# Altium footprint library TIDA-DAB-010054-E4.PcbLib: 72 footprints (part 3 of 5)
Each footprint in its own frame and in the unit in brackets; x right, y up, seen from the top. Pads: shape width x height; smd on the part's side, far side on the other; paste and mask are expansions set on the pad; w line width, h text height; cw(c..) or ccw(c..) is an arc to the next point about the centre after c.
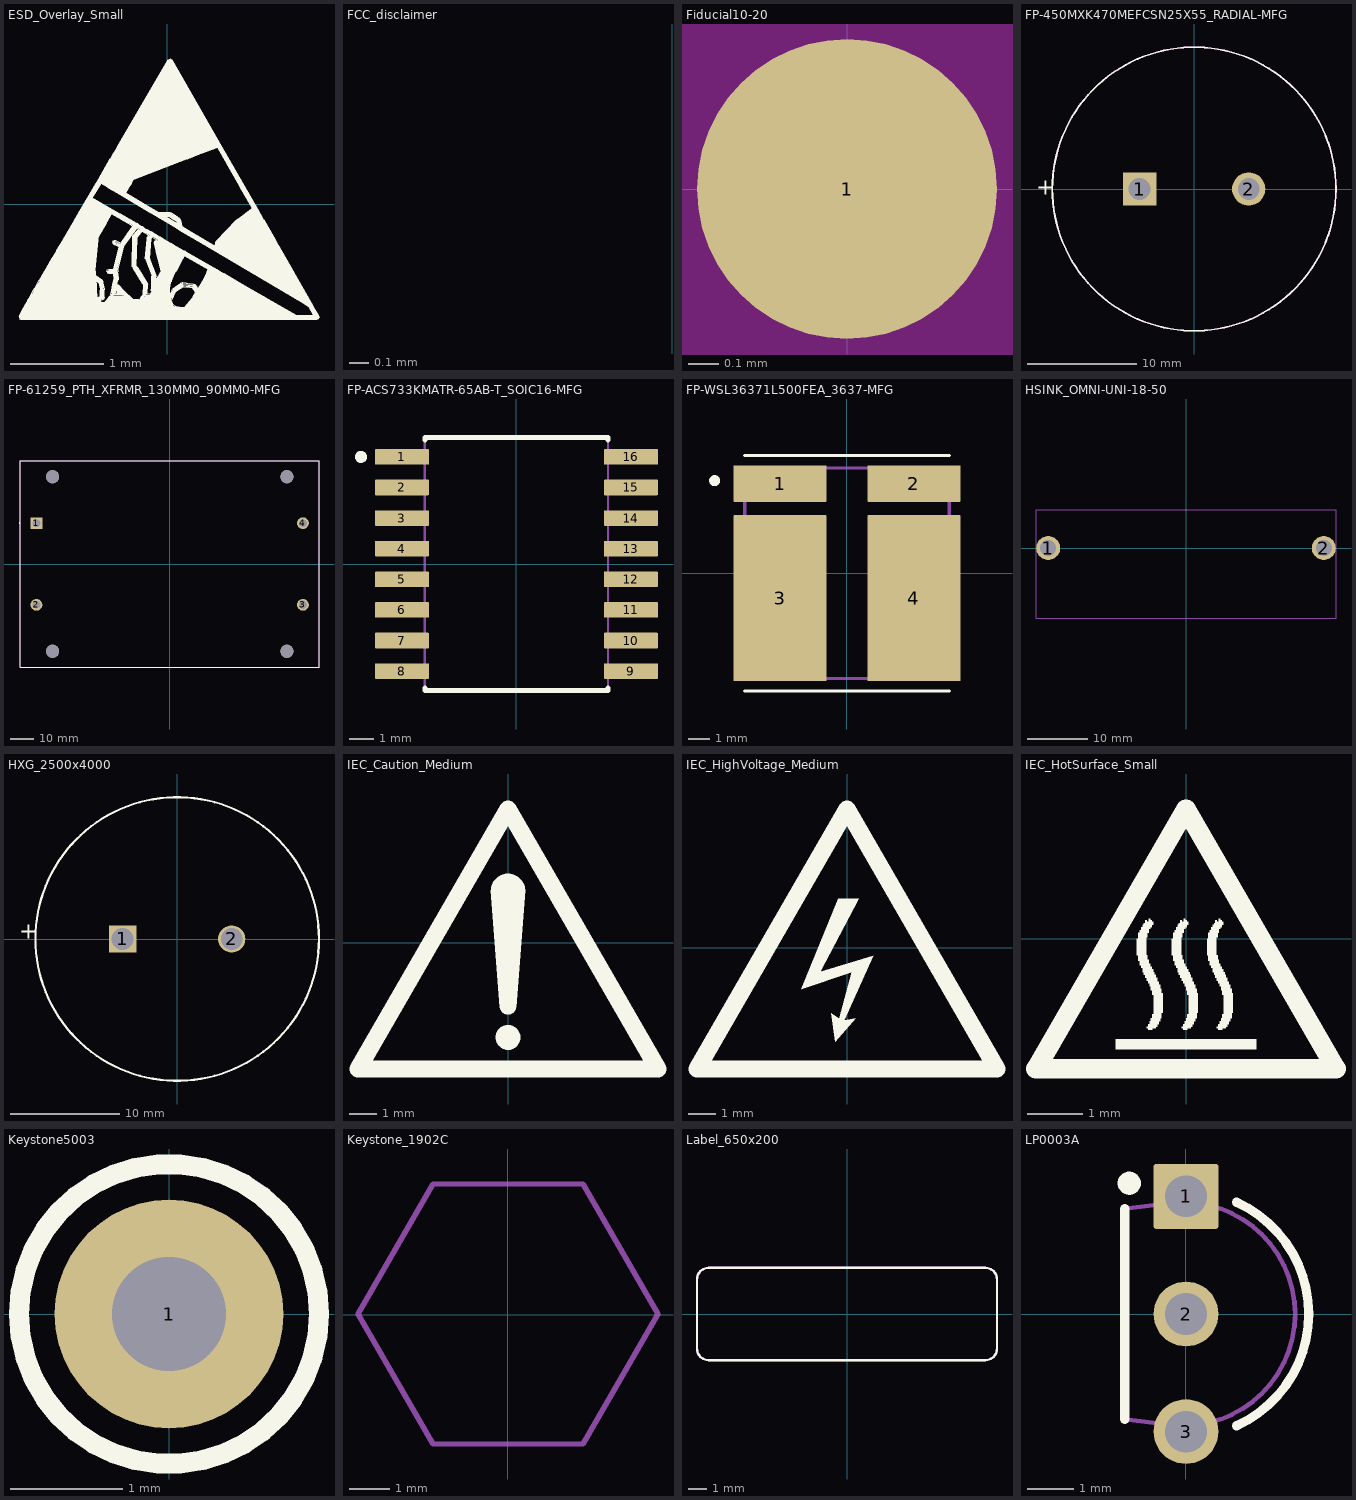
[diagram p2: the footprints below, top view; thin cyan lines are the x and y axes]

## ESD_Overlay_Small [mm]
height 9.2
Top Overlay:
  drawing of 901 lines, arcs and shapes, not listed

## FCC_disclaimer [mm]
height 9.2
Top Overlay:
  text "For evaluation only; not FCC approved for resale." at -1.598,12.423 h1.52

## Fiducial10-20 [mm]
height 9.2
pads (1):
  round 1 smd mask+0.5: 1(0,0)
Top Layer keep-out:
  circle w1.178: c0,0 r0.5

## FP-450MXK470MEFCSN25X55_RADIAL-MFG [mm]
pads (2):
  rrect3% 3.05x3.05 hole 2 paste-1000 mask+0: 1(-5,0)
  round 3.05 hole 2 paste-1000 mask+0: 2(5,0)
Top Overlay:
  circle w0.15: c0,0 r13
  text "+" at -14.5,-0.508 h1.5
Mechanical 5:
  circle w0.15: c0,0 r13
  text ".Designator" at -0.229,0.676 h0.51
  text "+" at -13.64,-0.492 h0.51
3D body "Cap_450MXK470MEFCSN25X55_RADIAL.STEP": height 0.25, standoff 0, extent -13.1,-13.1 13.1,13.1

## FP-61259_PTH_XFRMR_130MM0_90MM0-MFG [mm]
height 9.2
pads (8):
  rrect2% 5.15x5.15 hole 3.4 paste-1000 mask+0: 1(-58.02,17.78)
  round 5.15 hole 3.4 paste-1000 mask+0: 2(-58.02,-17.78) 4(58.02,17.78)
  round 5.15 hole 3.6 paste-1000 mask+0: 3(58.02,-17.78)
  round 5.7 hole 5.7 unplated paste-1000 mask+0: ""(-51,-38) ""(-51,38) ""(51,-38) ""(51,38)
Top Overlay:
  circle w0.25: c-65.5,17.78 r0.125
  lines w0.15: -65,-45 -65,45 65,45 65,-45 -65,-45
Mechanical 5:
  lines w0.15: -65,-45 -65,45 65,45 65,-45 -65,-45
  text ".Designator" at -58.167,24.194 h0.51
3D body "Payton Planar 61259 rev3.step": height 52, standoff 0, extent -65,-45 65,45

## FP-ACS733KMATR-65AB-T_SOIC16-MFG [mm]
height 9.2
pads (16):
  rrect15% 2.25x0.65 smd paste+0 mask+0: 1(-4.75,4.445) 2(-4.75,3.175) 3(-4.75,1.905) 4(-4.75,0.635) 5(-4.75,-0.635) 6(-4.75,-1.905) 7(-4.75,-3.175) 8(-4.75,-4.445) 9(4.75,-4.445) 10(4.75,-3.175) 11(4.75,-1.905) 12(4.75,-0.635) 13(4.75,0.635) 14(4.75,1.905) 15(4.75,3.175) 16(4.75,4.445)
Top Overlay:
  circle w0.25: c-6.45,4.445 r0.125
  lines w0.2: -3.8,-5.145 -3.8,-5.25 3.8,-5.25 3.8,-5.145 ; -3.8,5.145 -3.8,5.25 3.8,5.25 3.8,5.145
Mechanical 5:
  lines w0.1: -3.8,-5.25 -3.8,5.25 3.8,5.25 3.8,-5.25 -3.8,-5.25
  text ".Designator" at 0.134,-0.209 h0.51
3D body "IC_ACS733KMATR-65AB-T_SOIC16.STEP": height 0.25, standoff 0, extent -5.975,-5.35 5.975,5.35

## FP-WSL36371L500FEA_3637-MFG [mm]
height 9.2
pads (4):
  rrect6% 4.27x1.68 smd paste+0 mask+0: 1(-3.075,4.115) 2(3.075,4.115)
  rrect2% 4.27x7.62 smd paste+0 mask+0: 3(-3.075,-1.145) 4(3.075,-1.145)
Top Overlay:
  circle w0.25: c-6.075,4.25 r0.125
  lines w0.15: -4.697,-5.4 4.697,-5.4 ; -4.697,5.4 4.697,5.4
Mechanical 5:
  lines w0.15: -4.697,-4.827 -4.697,4.827 4.697,4.827 4.697,-4.827 -4.697,-4.827
  text ".Designator" at 0.686,-0.508 h0.51
3D body "Res_WSL36371L500FEA_3637.STEP": height 0.25, standoff 0, extent -5.31,-5.055 5.31,5.055

## HSINK_OMNI-UNI-18-50 [mm] "Heat Sink, TO-247, TO-264"
height 38.1
pads (2):
  round 4 hole 2.67: 1(-22.97,0) 2(22.97,0)
Mechanical 5:
  lines w0.1: -25,-11.665 -25,6.365 25,6.365 25,-11.665 -25,-11.665
  text ".Designator" at -0.179,-0.251 h0.51
3D body "OMNI-UNI-18-50.stp": height 35.6, standoff -5, extent -25,-11.665 25,6.365

## HXG_2500x4000 [mm] "TH, 2-Leads, Dia 25mm, Pin Spacing 10mm"
height 42
pads (2):
  rect 2.5x2.5 hole 2: 1(-5,0)
  round 2.5 hole 2: 2(5,0)
Top Overlay:
  circle w0.2: c0,0 r13
  text "+" at -14.5,0 h1.5
Mechanical 5:
  circle w0.1: c0,0 r13
  text "+" at -13.67,0.026 h0.51
  text ".Designator" at -0.386,0.762 h0.51
3D body: height 42, standoff 0, extent 11.2,-4.2 13.1,4.2
3D body: height 42, standoff 0, extent -11.905,-11.976 12,11.976
3D body: height 41.9, standoff 0.1, extent -12.897,-12.974 13,12.974
3D body: height 0, standoff -2.5, extent 4.132,-0.873 5.875,0.873
3D body: height 0, standoff -2.5, extent -5.868,-0.873 -4.125,0.873

## IEC_Caution_Medium [mm]
height 7.13
Top Overlay:
  circle w0.457: c0,-3.48 r0.229
  circle w0.635: c0,1.905 r0.318
  circle w0.305: c0,-2.337 r0.152
  region: -0.635,1.93 0.635,1.93 0.305,-2.362 -0.305,-2.362
  lines w0.635: -5.512,-4.635 0,4.911 5.512,-4.635 -5.512,-4.635

## IEC_HighVoltage_Medium [mm]
height 9.2
Top Overlay:
  region: -0.33,1.803 0.432,1.803 -0.991,-0.889 0.965,-0.305 -0.102,-2.667 0.33,-2.591 -0.432,-3.454 -0.584,-2.413 -0.279,-2.616 0.178,-0.914 -1.676,-1.524
  lines w0.635: -5.512,-4.458 5.512,-4.458 0,5.089 -5.512,-4.458

## IEC_HotSurface_Small [mm]
height 9.2
Top Overlay:
  drawing of 10 lines, arcs and shapes, not listed

## Keystone5003 [mil] "For Keystone 500x miniature loop terminals"
height 181.1
pads (1):
  round 80 hole 40: 1(0,0)
Top Overlay:
  circle w7: c0,0 r52.5
Mechanical 5:
  circle w3.94: c0,0 r52.5
  text ".Designator" at -14.84,134 h20
3D body "Keystone_5003.stp": height 181.97, standoff -118.11, extent -49,-49 49.04,49.24

## Keystone_1902C [mil] "Hex Standoff, 4-40 threaded, nylon"
height 500
pads (1):
  round 1 on Mech3: 0(0,0)
Mechanical 5:
  lines w5: -145.29,0.49 -72.56,-125.49 72.92,-125.49 145.65,0.49 72.92,126.47 -72.56,126.47 -145.29,0.49
  text ".Designator" at -60,-20 h20
3D body "Keystone_1902C.stp": height 501, standoff 1, extent -144.95,-125.98 146,125.98

## Label_650x200 [mil] "Thermal Transfer Label"
height 1
pads (1):
  round 1 on Mech13: 0(0,0)
Top Overlay:
  lines w5: -325,-75 ccw(c-300,-75) -300,-100 300,-100 ccw(c300,-75) 325,-75 325,75 ccw(c300,75) 300,100 -300,100 ccw(c-300,75) -325,75 -325,-75
Mechanical 5:
  lines w5: -325,-75 ccw(c-300,-75) -300,-100 300,-100 ccw(c300,-75) 325,-75 325,75 ccw(c300,75) 300,100 -300,100 ccw(c-300,75) -325,75 -325,-75
  text ".Designator" at 27,8 h20
3D body: height 1, standoff 0, extent -325.02,-100.02 325.02,100.02

## LP0003A [mm] "TO, Flat Index; 3 In-Line, Formed Axial Leads; Body Dia. 4.8mm; Leads 0.56 x 0.41 mm (max)"
height 9.33
pads (3):
  rrect7% 1.4x1.4 hole 0.9: 1(0,2.54)
  round 1.4 hole 0.9: 2(0,0) 3(0,-2.54)
Top Overlay:
  circle w0.25: c-1.225,2.825 r0.125
  lines w0.2: -1.325,-2.273 -1.325,2.273 ; 1.092,-2.415 ccw(c0,0) 1.092,2.415
Mechanical 5:
  lines w0.1: 0.195,-2.4 0.195,-2.722 0.195,-2.83 -0.185,-2.83 -0.185,-2.722 -0.185,-2.412 ; 0.195,2.4 0.195,2.722 0.195,2.83 -0.185,2.83 -0.185,2.722 -0.185,2.412 ; -0.185,-2.412 -1.325,-2.273 -1.325,2.273 -0.185,2.412 ; -0.185,-2.412 -0.055,-2.412 ccw(c-0.055,0) -0.055,2.412 -0.185,2.412
  text ".Designator" at -0.694,4.545 h0.51
3D body "LP0003B.stp": height 9.01, standoff -8.51, extent -1.333,-2.83 2.349,2.83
